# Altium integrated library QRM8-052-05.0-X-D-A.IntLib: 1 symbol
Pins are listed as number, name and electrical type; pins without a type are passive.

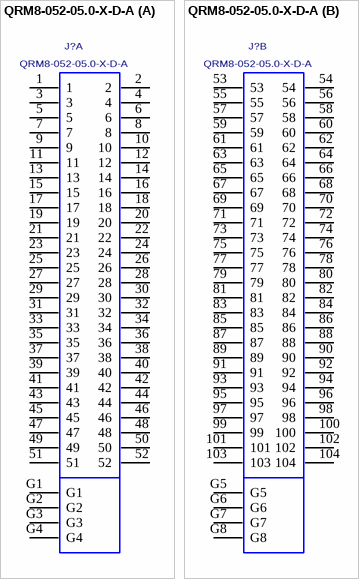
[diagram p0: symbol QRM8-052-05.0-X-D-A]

## QRM8-052-05.0-X-D-A
designator J?
.8mm Q-Rate Terminal Assembly,104 PINS.; MANUFACTURER: SAMTEC
footprint QRM8-052-05.0-X-D-A
part A pins: 1, 2, 3, 4, 5, 6, 7, 8, 9, 10, 11, 12, 13, 14, 15, 16, 17, 18, 19, 20, 21, 22, 23, 24, 25, 26, 27, 28, 29, 30, 31, 32, 33, 34, 35, 36, 37, 38, 39, 40, 41, 42, 43, 44, 45, 46, 47, 48, 49, 50, 51, 52, G1, G2, G3, G4
part B pins: 53, 54, 55, 56, 57, 58, 59, 60, 61, 62, 63, 64, 65, 66, 67, 68, 69, 70, 71, 72, 73, 74, 75, 76, 77, 78, 79, 80, 81, 82, 83, 84, 85, 86, 87, 88, 89, 90, 91, 92, 93, 94, 95, 96, 97, 98, 99, 100, 101, 102, 103, 104, G5, G6, G7, G8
